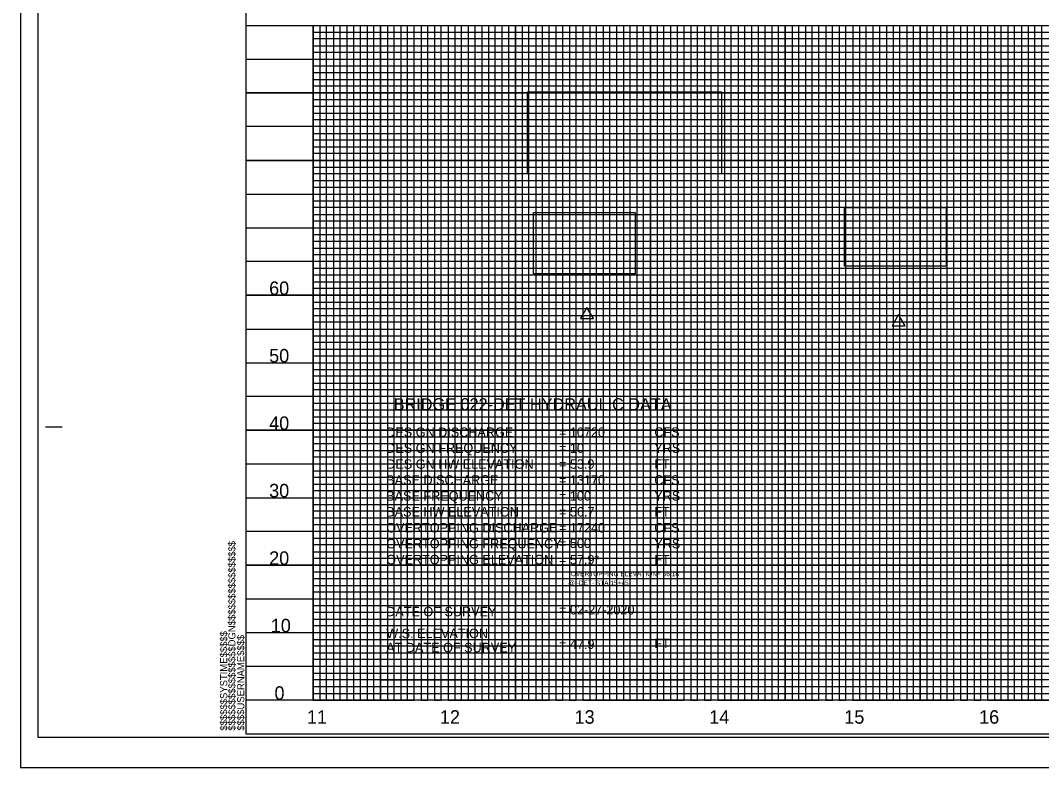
# Model space of a CAD drawing. Extents: x 1019474 to 1021161, y 504129 to 505324.
# Drawn here: x 1019474 to 1020231, y 504129 to 504683 of the extents above; entities that cross this region are included whole.
import ezdxf

# ---------------------------------------------------------------- set-up
doc = ezdxf.new("R2010")
doc.units = 0
for name, color, linetype in [('Exist Vertical Profile Horizontal Axis Label Major', 7, 'Continuous'), ('Exist Vertical Profile Vertical Axis Label', 7, 'Continuous'), ('Prop Grid Mask', 7, 'Continuous'), ('Prop Roadway Bridge', 7, 'Continuous'), ('Prop Vertical Profile Curve Label', 7, 'Continuous'), ('Sheet Cutting Line CELL', 7, 'Continuous'), ('Sheet DOT Grid CELL', 7, 'Continuous'), ('Sheet Layout Profile Border Port 2', 7, 'Continuous'), ('Sheet Plot Border Inside CELL', 7, 'Continuous'), ('Sheet Plot Border Outside CELL', 7, 'Continuous'), ('Sheet Profile CELL', 7, 'Continuous'), ('Sheet Profile Grid Major CELL', 7, 'Continuous'), ('Sheet Profile Grid Middle CELL', 7, 'Continuous'), ('Sheet Profile Grid Minor CELL', 7, 'Continuous')]:
    doc.layers.add(name, color=color, linetype=linetype)

msp = doc.modelspace()

# ---------------------------------------------------------------- linework, layer by layer
at = {"layer": 'Prop Grid Mask'}
for points in [[(1019850.13, 504630.08), (1019994, 504630.08), (1019994, 504569.37), (1019850.13, 504569.37)], [(1019854.53, 504540.77), (1019929.98, 504540.77), (1019929.98, 504495.24), (1019854.53, 504495.24)], [(1020085.14, 504544.3), (1020160.6, 504544.3), (1020160.6, 504500.89), (1020085.14, 504500.89)], [(1019741.22, 504194.29), (1019966.22, 504194.29), (1019966.22, 504419.29), (1019741.22, 504419.29)]]:
    msp.add_lwpolyline(points, close=True, dxfattribs=at)
at = {"layer": 'Prop Vertical Profile Curve Label'}
for points in [[(1019889.46, 504462.09), (1019898.98, 504462.09), (1019894.22, 504470.34)], [(1020120.46, 504456.7), (1020129.98, 504456.7), (1020125.22, 504464.95)]]:
    msp.add_lwpolyline(points, close=True, dxfattribs=at)
at = {"layer": 'Sheet Cutting Line CELL'}
for p, q in [((1019474.22, 505229.29), (1019474.22, 504129.29)), ((1019474.22, 504129.29), (1021158.22, 504129.29))]:
    msp.add_line(p, q, dxfattribs=at)
at = {"layer": 'Sheet DOT Grid CELL'}
for p, q in [((1019641.22, 504679.29), (1021141.11, 504679.29)), ((1019691.22, 504679.29), (1019691.22, 504179.29)), ((1019741.22, 504679.29), (1019741.22, 504179.29)), ((1019791.22, 504679.29), (1019791.22, 504179.29)), ((1019841.22, 504679.29), (1019841.22, 504179.29)), ((1019891.22, 504679.29), (1019891.22, 504179.29)), ((1019941.22, 504679.29), (1019941.22, 504179.29)), ((1019991.22, 504679.29), (1019991.22, 504179.29)), ((1020041.22, 504679.29), (1020041.22, 504179.29)), ((1020091.22, 504679.29), (1020091.22, 504179.29)), ((1020141.22, 504679.29), (1020141.22, 504179.29)), ((1020191.22, 504679.29), (1020191.22, 504179.29)), ((1019641.22, 504629.29), (1021141.11, 504629.29)), ((1019641.22, 504579.29), (1021141.11, 504579.29)), ((1019641.22, 504529.29), (1021141.11, 504529.29)), ((1019641.22, 504479.29), (1021141.11, 504479.29)), ((1019641.22, 504429.29), (1021141.11, 504429.29)), ((1019641.22, 504379.29), (1021141.11, 504379.29)), ((1019641.22, 504329.29), (1021141.11, 504329.29)), ((1019641.22, 504279.29), (1021141.11, 504279.29)), ((1019641.22, 504229.29), (1021141.11, 504229.29))]:
    msp.add_line(p, q, dxfattribs=at)
at = {"layer": 'Sheet Layout Profile Border Port 2'}
msp.add_lwpolyline([(1019691.22, 504679.29), (1021091.22, 504679.29), (1021091.22, 504179.29), (1019691.22, 504179.29)], close=True, dxfattribs=at)
at = {"layer": 'Sheet Plot Border Inside CELL'}
msp.add_lwpolyline([(1019487.22, 504151.74), (1021153.72, 504151.74), (1021153.72, 505206.84), (1019487.22, 505206.84)], close=True, dxfattribs=at)
at = {"layer": 'Sheet Plot Border Outside CELL'}
msp.add_lwpolyline([(1019474.22, 504129.29), (1021158.22, 504129.29), (1021158.22, 505229.29), (1019474.22, 505229.29)], close=True, dxfattribs=at)
at = {"layer": 'Sheet Profile CELL'}
for p, q in [((1019641.22, 504679.29), (1021141.22, 504679.29)), ((1019492.72, 504381.79), (1019505.22, 504381.79)), ((1021141.22, 504179.29), (1019641.22, 504179.29)), ((1019641.22, 504154.29), (1021141.22, 504154.29)), ((1019641.22, 504154.29), (1019641.22, 504154.29)), ((1019641.22, 504154.29), (1019641.22, 504154.29)), ((1019641.22, 504154.29), (1019641.22, 504154.29)), ((1019641.22, 504154.29), (1019641.22, 504154.29)), ((1019641.22, 504154.29), (1019641.22, 504154.29)), ((1019641.22, 504154.29), (1019641.22, 504154.29)), ((1019641.22, 504154.29), (1019641.22, 504154.29))]:
    msp.add_line(p, q, dxfattribs=at)
msp.add_lwpolyline([(1021141.22, 505204.29), (1019641.22, 505204.29), (1019641.22, 504154.29), (1021141.22, 504154.29)], close=True, dxfattribs=at)
msp.add_lwpolyline([(1019678.72, 504154.29), (1019678.72, 504154.29)], dxfattribs=at)
at = {"layer": 'Sheet Profile Grid Major CELL'}
for p, q in [((1020141.22, 504679.29), (1020191.22, 504679.29)), ((1019641.22, 504179.29), (1019641.22, 504179.29))]:
    msp.add_line(p, q, dxfattribs=at)
for points in [[(1019691.22, 504679.29), (1019691.22, 504179.29), (1019741.22, 504179.29), (1019741.22, 504679.29), (1019791.22, 504679.29), (1019791.22, 504179.29), (1019841.22, 504179.29), (1019841.22, 504679.29), (1019891.22, 504679.29), (1019891.22, 504179.29), (1019941.22, 504179.29), (1019941.22, 504679.29), (1019991.22, 504679.29), (1019991.22, 504179.29), (1020041.22, 504179.29), (1020041.22, 504679.29), (1020091.22, 504679.29), (1020091.22, 504179.29), (1020141.22, 504179.29), (1020141.22, 504679.29), (1020191.22, 504679.29), (1020191.22, 504179.29), (1020241.22, 504179.29)], [(1021141.22, 504629.29), (1019641.22, 504629.29)], [(1021141.22, 504579.29), (1019641.22, 504579.29), (1019641.22, 504529.29), (1021141.22, 504529.29)], [(1021141.22, 504479.29), (1019641.22, 504479.29), (1019641.22, 504429.29), (1021141.22, 504429.29)], [(1021141.22, 504379.29), (1019641.22, 504379.29), (1019641.22, 504329.29), (1021141.22, 504329.29)], [(1021141.22, 504279.29), (1019641.22, 504279.29), (1019641.22, 504279.29), (1019641.22, 504229.29), (1021141.22, 504229.29)], [(1021141.22, 504179.29), (1019641.22, 504179.29)]]:
    msp.add_lwpolyline(points, dxfattribs=at)
at = {"layer": 'Sheet Profile Grid Middle CELL'}
for points in [[(1019666.22, 504679.29), (1019716.22, 504679.29), (1019716.22, 504179.29), (1019766.22, 504179.29), (1019766.22, 504679.29), (1019816.22, 504679.29), (1019816.22, 504179.29), (1019866.22, 504179.29), (1019866.22, 504679.29), (1019916.22, 504679.29), (1019916.22, 504179.29), (1019966.22, 504179.29), (1019966.22, 504679.29), (1020016.22, 504679.29), (1020016.22, 504179.29), (1020066.22, 504179.29), (1020066.22, 504679.29), (1020116.22, 504679.29), (1020116.22, 504179.29), (1020166.22, 504179.29), (1020166.22, 504679.29), (1020216.22, 504679.29), (1020216.22, 504179.29), (1020266.22, 504179.29)], [(1019641.22, 504654.29), (1021141.22, 504654.29)], [(1021141.22, 504604.29), (1019641.22, 504604.29), (1019641.22, 504554.29), (1021141.22, 504554.29)], [(1021141.22, 504504.29), (1019641.22, 504504.29), (1019641.22, 504454.29), (1021141.22, 504454.29)], [(1021141.22, 504404.29), (1019641.22, 504404.29), (1019641.22, 504354.29), (1021141.22, 504354.29)], [(1021141.22, 504304.29), (1019641.22, 504304.29), (1019641.22, 504254.29), (1021141.22, 504254.29)], [(1021141.22, 504204.29), (1019641.22, 504204.29)]]:
    msp.add_lwpolyline(points, dxfattribs=at)
at = {"layer": 'Sheet Profile Grid Minor CELL'}
for p, q in [((1019691.22, 504674.29), (1021091.22, 504674.29)), ((1021091.22, 504669.29), (1019691.22, 504669.29)), ((1019691.22, 504664.29), (1021091.22, 504664.29)), ((1021091.22, 504659.29), (1019691.22, 504659.29)), ((1019691.22, 504649.29), (1021091.22, 504649.29)), ((1021091.22, 504644.29), (1019691.22, 504644.29)), ((1019691.22, 504639.29), (1021091.22, 504639.29)), ((1021091.22, 504634.29), (1019691.22, 504634.29)), ((1019691.22, 504624.29), (1021091.22, 504624.29)), ((1021091.22, 504619.29), (1019691.22, 504619.29)), ((1019691.22, 504614.29), (1021091.22, 504614.29)), ((1021091.22, 504609.29), (1019691.22, 504609.29)), ((1019691.22, 504599.29), (1021091.22, 504599.29)), ((1021091.22, 504594.29), (1019691.22, 504594.29)), ((1019691.22, 504589.29), (1021091.22, 504589.29)), ((1021091.22, 504584.29), (1019691.22, 504584.29)), ((1019691.22, 504574.29), (1021091.22, 504574.29)), ((1021091.22, 504569.29), (1019691.22, 504569.29)), ((1019691.22, 504564.29), (1021091.22, 504564.29)), ((1021091.22, 504559.29), (1019691.22, 504559.29)), ((1019691.22, 504549.29), (1021091.22, 504549.29)), ((1021091.22, 504544.29), (1019691.22, 504544.29)), ((1019691.22, 504539.29), (1021091.22, 504539.29)), ((1021091.22, 504534.29), (1019691.22, 504534.29)), ((1019691.22, 504524.29), (1021091.22, 504524.29)), ((1021091.22, 504519.29), (1019691.22, 504519.29)), ((1019691.22, 504514.29), (1021091.22, 504514.29)), ((1021091.22, 504509.29), (1019691.22, 504509.29)), ((1019691.22, 504499.29), (1021091.22, 504499.29)), ((1021091.22, 504494.29), (1019691.22, 504494.29)), ((1019691.22, 504489.29), (1021091.22, 504489.29)), ((1021091.22, 504484.29), (1019691.22, 504484.44)), ((1019691.22, 504474.29), (1021091.22, 504474.29)), ((1021091.22, 504469.29), (1019691.22, 504469.29)), ((1019691.22, 504464.29), (1021091.22, 504464.29)), ((1021091.22, 504459.29), (1019691.22, 504459.29)), ((1019691.22, 504449.29), (1021091.22, 504449.29)), ((1021091.22, 504444.29), (1019691.22, 504444.29)), ((1019691.22, 504439.29), (1021091.22, 504439.29)), ((1021091.22, 504434.29), (1019691.22, 504434.29)), ((1019691.22, 504424.29), (1021091.22, 504424.29)), ((1021091.22, 504419.29), (1019691.22, 504419.29)), ((1019691.22, 504414.29), (1021091.22, 504414.29)), ((1021091.22, 504409.29), (1019691.22, 504409.29)), ((1019691.22, 504399.29), (1021091.22, 504399.29)), ((1021091.22, 504394.29), (1019691.22, 504394.29)), ((1019691.22, 504389.29), (1021091.22, 504389.29)), ((1021091.22, 504384.29), (1019691.22, 504384.29)), ((1019691.22, 504374.29), (1021091.22, 504374.29)), ((1021091.22, 504369.29), (1019691.22, 504369.29)), ((1019691.22, 504364.29), (1021091.22, 504364.29)), ((1021091.22, 504359.29), (1019691.22, 504359.29)), ((1019691.22, 504349.29), (1021091.22, 504349.29)), ((1021091.22, 504344.29), (1019691.22, 504344.29)), ((1019691.22, 504339.29), (1021091.22, 504339.29)), ((1021091.22, 504334.29), (1019691.22, 504334.29)), ((1019691.22, 504324.29), (1021091.22, 504324.29)), ((1021091.22, 504319.29), (1019691.22, 504319.29)), ((1019691.22, 504314.29), (1021091.22, 504314.29)), ((1021091.22, 504309.29), (1019691.22, 504309.29)), ((1019691.22, 504299.29), (1021091.22, 504299.29)), ((1021091.22, 504294.29), (1019691.22, 504294.29)), ((1019691.22, 504289.29), (1021091.22, 504289.29)), ((1021091.22, 504284.29), (1019691.22, 504284.29)), ((1019691.22, 504274.29), (1020891.22, 504274.29)), ((1020891.22, 504269.29), (1019691.22, 504269.29)), ((1019691.22, 504264.29), (1020891.22, 504264.29)), ((1020891.22, 504259.29), (1019691.22, 504259.29)), ((1019691.22, 504249.29), (1021091.22, 504249.29)), ((1021091.22, 504244.29), (1019691.22, 504244.29)), ((1019691.22, 504239.29), (1021091.22, 504239.29)), ((1021091.22, 504234.29), (1019691.22, 504234.29)), ((1019691.22, 504224.29), (1021091.22, 504224.29)), ((1021091.22, 504219.29), (1019691.22, 504219.29)), ((1019691.22, 504214.29), (1021091.22, 504214.29)), ((1021091.22, 504209.29), (1019691.22, 504209.29)), ((1019691.22, 504199.29), (1021091.22, 504199.29)), ((1021091.22, 504194.29), (1019691.22, 504194.29)), ((1019691.22, 504189.29), (1021091.22, 504189.29)), ((1019691.22, 504184.29), (1021091.22, 504184.29))]:
    msp.add_line(p, q, dxfattribs=at)
for points in [[(1019691.22, 504679.29), (1019696.22, 504679.29), (1019696.22, 504179.29), (1019701.22, 504179.29), (1019701.22, 504679.29), (1019706.22, 504679.29), (1019706.22, 504179.29), (1019711.22, 504179.29), (1019711.22, 504679.29), (1019721.22, 504679.29), (1019721.22, 504179.29), (1019726.22, 504179.29), (1019726.22, 504679.29), (1019731.22, 504679.29), (1019731.22, 504179.29), (1019736.22, 504179.29), (1019746.22, 504179.29), (1019751.22, 504179.29), (1019751.22, 504679.29), (1019756.22, 504679.29), (1019756.22, 504179.29), (1019761.22, 504179.29), (1019761.22, 504679.29), (1019771.22, 504679.29), (1019771.22, 504179.29), (1019776.22, 504179.29), (1019776.22, 504679.29), (1019781.22, 504679.29), (1019781.22, 504179.29), (1019786.22, 504179.29), (1019786.22, 504679.29), (1019796.22, 504679.29), (1019796.22, 504179.29), (1019801.22, 504179.29), (1019801.22, 504679.29), (1019806.22, 504679.29), (1019806.22, 504179.29), (1019811.22, 504179.29), (1019811.22, 504679.29), (1019821.22, 504679.29), (1019821.22, 504179.29), (1019826.22, 504179.29), (1019826.22, 504679.29), (1019831.22, 504679.29), (1019831.22, 504179.29), (1019836.22, 504179.29), (1019836.22, 504679.29), (1019846.22, 504679.29), (1019846.22, 504179.29), (1019851.22, 504179.29), (1019851.22, 504679.29), (1019856.22, 504679.29), (1019856.22, 504179.29), (1019861.22, 504179.29), (1019861.22, 504679.29), (1019871.22, 504679.29), (1019871.22, 504179.29), (1019876.22, 504179.29), (1019876.22, 504679.29), (1019881.22, 504679.29), (1019881.22, 504179.29), (1019886.22, 504179.29), (1019886.22, 504679.29), (1019896.22, 504679.29), (1019896.22, 504179.29), (1019901.22, 504179.29), (1019901.22, 504679.29), (1019906.22, 504679.29), (1019906.22, 504179.29)], [(1019736.22, 504179.29), (1019736.22, 504679.29), (1019746.22, 504679.29), (1019746.22, 504179.29)], [(1019906.22, 504179.29), (1019911.22, 504179.29), (1019911.22, 504679.29), (1019921.22, 504679.29), (1019921.22, 504179.29), (1019926.22, 504179.29), (1019926.22, 504679.29), (1019931.22, 504679.29), (1019931.22, 504179.29), (1019936.22, 504179.29), (1019936.22, 504679.29), (1019946.22, 504679.29), (1019946.22, 504179.29), (1019951.22, 504179.29), (1019951.22, 504679.29), (1019956.22, 504679.29), (1019956.22, 504179.29), (1019961.22, 504179.29), (1019961.22, 504679.29), (1019971.22, 504679.29), (1019971.22, 504179.29), (1019976.22, 504179.29), (1019976.22, 504679.29), (1019981.22, 504679.29), (1019981.22, 504179.29), (1019986.22, 504179.29), (1019986.22, 504679.29), (1019996.22, 504679.29), (1019996.22, 504179.29), (1020001.22, 504179.29), (1020001.22, 504679.29), (1020006.22, 504679.29), (1020006.22, 504179.29), (1020011.22, 504179.29), (1020011.22, 504679.29), (1020021.22, 504679.29), (1020021.22, 504179.29), (1020026.22, 504179.29), (1020026.22, 504679.29), (1020031.22, 504679.29), (1020031.22, 504179.29), (1020036.22, 504179.29), (1020036.22, 504679.29), (1020046.22, 504679.29), (1020046.22, 504179.29), (1020051.22, 504179.29), (1020051.22, 504679.29), (1020056.22, 504679.29), (1020056.22, 504179.29), (1020061.22, 504179.29), (1020061.22, 504679.29), (1020071.22, 504679.29), (1020071.22, 504179.29), (1020076.22, 504179.29), (1020076.22, 504679.29), (1020081.22, 504679.29), (1020081.22, 504179.29), (1020086.22, 504179.29), (1020086.22, 504679.29), (1020096.22, 504679.29), (1020096.22, 504179.29), (1020101.22, 504179.29), (1020101.22, 504679.29), (1020106.22, 504679.29), (1020106.22, 504179.29), (1020111.22, 504179.29), (1020111.22, 504679.29), (1020121.22, 504679.29), (1020121.22, 504179.29), (1020126.22, 504179.29), (1020126.22, 504679.29), (1020131.22, 504679.29), (1020131.22, 504179.29), (1020136.22, 504179.29), (1020136.22, 504679.29), (1020146.22, 504679.29), (1020146.22, 504179.29), (1020151.22, 504179.29), (1020151.22, 504679.29), (1020156.22, 504679.29), (1020156.22, 504179.29), (1020161.22, 504179.29), (1020161.22, 504679.29), (1020171.22, 504679.29), (1020171.22, 504179.29), (1020176.22, 504179.29), (1020176.22, 504679.29), (1020181.22, 504679.29), (1020181.22, 504179.29), (1020186.22, 504179.29), (1020186.22, 504679.29), (1020196.22, 504679.29), (1020196.22, 504179.29), (1020201.22, 504179.29), (1020201.22, 504679.29), (1020206.22, 504679.29), (1020206.22, 504179.29), (1020211.22, 504179.29), (1020211.22, 504679.29), (1020221.22, 504679.29)], [(1020221.22, 504679.29), (1020221.22, 504179.29), (1020226.22, 504179.29), (1020226.22, 504679.29), (1020231.22, 504679.29), (1020231.22, 504179.29), (1020236.22, 504179.29)]]:
    msp.add_lwpolyline(points, dxfattribs=at)

# ---------------------------------------------------------------- texts
at = {"layer": 'Exist Vertical Profile Horizontal Axis Label Major'}
for s, p in [('11', (1019686.64, 504161.79)), ('12', (1019785.19, 504161.79)), ('13', (1019885.03, 504161.79)), ('14', (1019984.87, 504161.79)), ('15', (1020084.96, 504161.79)), ('16', (1020184.9, 504161.79))]:
    msp.add_text(s, height=10, dxfattribs=at).set_placement(p)
at = {"layer": 'Exist Vertical Profile Vertical Axis Label'}
for s, p in [('60', (1019658.61, 504479.54)), ('50', (1019658.61, 504429.54)), ('40', (1019658.61, 504379.54)), ('30', (1019658.61, 504329.54)), ('20', (1019658.61, 504279.54)), ('10', (1019659.8, 504229.54)), ('0', (1019662.56, 504179.54))]:
    msp.add_text(s, height=10, dxfattribs=at).set_placement(p)
at = {"layer": 'Prop Roadway Bridge'}
for s, height, p in [('BRIDGE 022-DET HYDRAULIC DATA', 9, (1019750.97, 504394.04)), ('CFS', 7, (1019944.14, 504374.44)), ('DESIGN DISCHARGE', 7, (1019745.42, 504374.34)), ('= 10720', 7, (1019873.49, 504374.34)), ('DESIGN FREQUENCY', 7, (1019745.42, 504362.54)), ('= 10', 7, (1019873.49, 504362.54)), ('YRS', 7, (1019944.14, 504362.54)), ('DESIGN HW ELEVATION', 7, (1019745.42, 504350.74)), ('= 53.9', 7, (1019873.49, 504350.74)), ('FT', 7, (1019944.14, 504350.74)), ('BASE DISCHARGE', 7, (1019745.42, 504338.94)), ('= 13170', 7, (1019873.49, 504338.94)), ('CFS', 7, (1019944.14, 504338.94)), ('BASE FREQUENCY', 7, (1019745.42, 504327.14)), ('= 100', 7, (1019873.49, 504327.14)), ('YRS', 7, (1019944.14, 504327.14)), ('BASE HW ELEVATION', 7, (1019745.42, 504315.34)), ('= 56.7', 7, (1019873.49, 504315.34)), ('FT', 7, (1019944.14, 504315.34)), ('OVERTOPPING DISCHARGE', 7, (1019745.42, 504303.54)), ('= 17240', 7, (1019873.49, 504303.54)), ('CFS', 7, (1019944.14, 504303.54)), ('OVERTOPPING FREQUENCY', 7, (1019745.42, 504291.74)), ('= 500', 7, (1019873.49, 504292.04)), ('YRS', 7, (1019944.14, 504291.74)), ('OVERTOPPING ELEVATION', 7, (1019745.42, 504279.94)), ('= 57.9*', 7, (1019873.49, 504279.94)), ('FT', 7, (1019944.14, 504279.94)), ("*OVERTOPPING ELEVATION= 56.18'", 3.5, (1019880.34, 504271.14)), ('@ -DET- STA 15+45', 3.5, (1019880.34, 504264.36)), ('DATE OF SURVEY', 7, (1019745.42, 504241.44)), ('= 02-27-2020', 7, (1019873.49, 504242.74)), ('W.S. ELEVATION', 7, (1019745.42, 504225.24)), ('= 47.9', 7, (1019873.49, 504217.19)), ('FT', 7, (1019944.14, 504217.79)), ('AT DATE OF SURVEY', 7, (1019745.42, 504214.74))]:
    msp.add_text(s, height=height, dxfattribs=at).set_placement(p)
at = {"layer": 'Sheet Profile CELL'}
for s, p in [('$$$$$$$$$$$$$$$$DGN$$$$$$$$$$$$$$$$', (1019633.58, 504156.67)), ('$$$$$$SYSTIME$$$$$', (1019627.53, 504156.67)), ('$$$$USERNAME$$$$', (1019640.16, 504156.68))]:
    msp.add_text(s, height=5.25, rotation=90, dxfattribs=at).set_placement(p)

doc.saveas('drawing.dxf')
